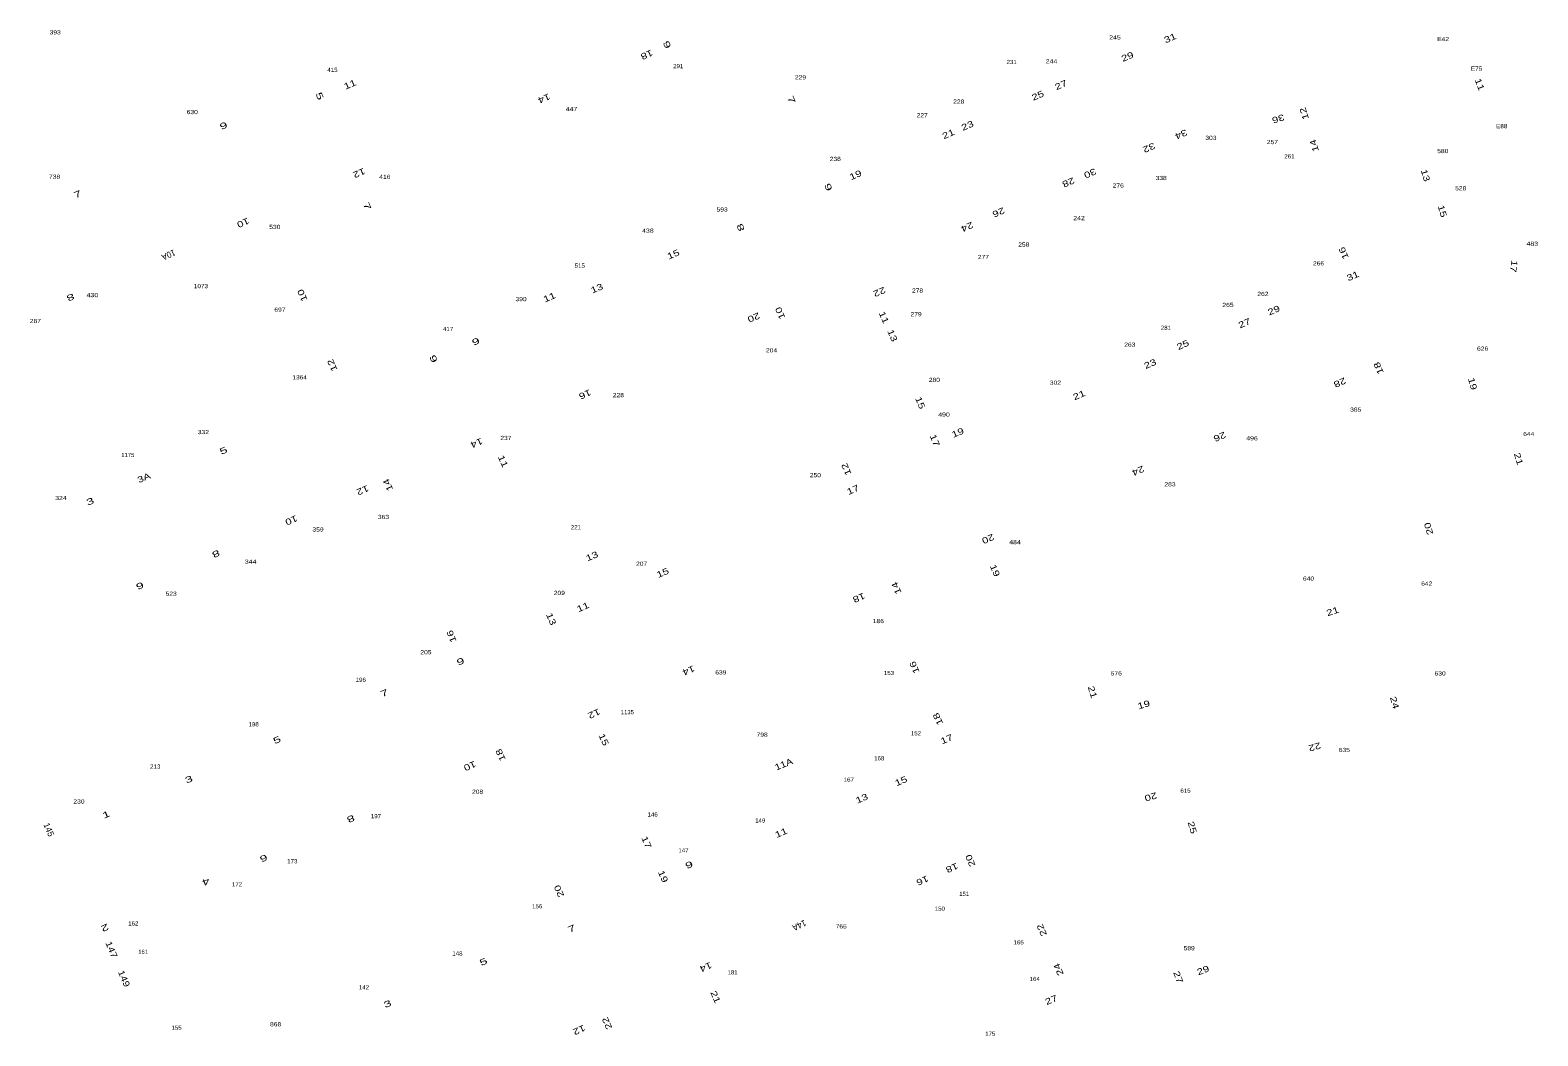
# Model space of a CAD drawing. Extents: x -828673 to -815583, y -1077737 to -1063807.
# Drawn here: x -820515.3 to -820153.1, y -1074088.1 to -1073846.6 of the extents above; entities that cross this region are included whole.
import ezdxf
from ezdxf.enums import TextEntityAlignment as Align

# ---------------------------------------------------------------- set-up
doc = ezdxf.new("R2010")
doc.units = 0
doc.header["$LTSCALE"] = 0.4
doc.layers.add('1', color=7, linetype='Continuous')
doc.layers.add('2', color=7, linetype='Continuous')

msp = doc.modelspace()

# ---------------------------------------------------------------- texts
at = {"layer": '1'}
for s, width, p in [('393', 1.2, (-820509.255, -1073847.574)), ('245', 1.25, (-820254.673, -1073848.798)), ('E42', 1.2, (-820175.857, -1073849.194)), ('291', 1.1, (-820359.582, -1073855.691)), ('231', 1.1, (-820279.5, -1073854.701)), ('244', 1.25, (-820269.913, -1073854.537)), ('415', 1.1, (-820442.65, -1073856.599)), ('229', 1.2, (-820330.22, -1073858.39)), ('E75', 1.15, (-820167.809, -1073856.29)), ('630', 1.2, (-820476.328, -1073866.738)), ('447', 1.25, (-820385.218, -1073866.008)), ('228', 1.2, (-820292.2, -1073864.211)), ('227', 1.2, (-820300.968, -1073867.491)), ('E88', 1.15, (-820161.776, -1073870.112)), ('303', 1.2, (-820231.631, -1073872.926)), ('257', 1.2, (-820216.866, -1073873.941)), ('261', 1.1, (-820212.763, -1073877.37)), ('580', 1.2, (-820175.925, -1073876.105)), ('238', 1.2, (-820321.862, -1073877.985)), ('738', 1.2, (-820509.395, -1073882.263)), ('416', 1.2, (-820430.06, -1073882.293)), ('276', 1.2, (-820253.892, -1073884.373)), ('338', 1.2, (-820243.579, -1073882.568)), ('528', 1.2, (-820171.623, -1073885.038)), ('593', 1.2, (-820349.043, -1073890.125)), ('242', 1.25, (-820263.303, -1073892.21)), ('530', 1.2, (-820456.491, -1073894.32)), ('438', 1.25, (-820366.879, -1073895.215)), ('258', 1.2, (-820276.577, -1073898.554)), ('483', 1.25, (-820154.416, -1073898.357)), ('277', 1.2, (-820286.27, -1073901.543)), ('266', 1.2, (-820205.775, -1073903.082)), ('515', 1.1, (-820383.236, -1073903.609)), ('1073', 1.15, (-820474.234, -1073908.541)), ('278', 1.2, (-820302.105, -1073909.606)), ('430', 1.25, (-820500.328, -1073910.704)), ('390', 1.2, (-820397.343, -1073911.675)), ('265', 1.2, (-820227.528, -1073913.062)), ('262', 1.2, (-820219.131, -1073910.412)), ('287', 1.2, (-820514.008, -1073916.925)), ('697', 1.2, (-820455.26, -1073914.205)), ('279', 1.2, (-820302.444, -1073915.301)), ('417', 1.1, (-820414.871, -1073918.85)), ('281', 1.1, (-820242.435, -1073918.547)), ('204', 1.2, (-820337.172, -1073923.969)), ('263', 1.2, (-820251.113, -1073922.607)), ('626', 1.2, (-820166.357, -1073923.554)), ('1364', 1.15, (-820450.524, -1073930.455)), ('280', 1.2, (-820298.057, -1073931.065)), ('302', 1.2, (-820268.978, -1073931.742)), ('228', 1.2, (-820373.969, -1073934.735)), ('385', 1.2, (-820196.847, -1073938.212)), ('490', 1.25, (-820295.747, -1073939.411)), ('332', 1.2, (-820473.655, -1073943.602)), ('237', 1.2, (-820400.984, -1073945.016)), ('496', 1.25, (-820221.764, -1073945.11)), ('644', 1.2, (-820155.28, -1073944.07)), ('1175', 1.05, (-820491.797, -1073949.114)), ('250', 1.2, (-820326.644, -1073953.956)), ('283', 1.2, (-820241.462, -1073956.146)), ('324', 1.25, (-820507.87, -1073959.44)), ('363', 1.2, (-820430.397, -1073963.989)), ('359', 1.2, (-820446.116, -1073967.004)), ('221', 1.1, (-820384.155, -1073966.463)), ('484', 1.25, (-820278.69, -1073970.041)), ('344', 1.25, (-820462.307, -1073974.749)), ('207', 1.2, (-820368.388, -1073975.237)), ('640', 1.2, (-820208.17, -1073978.8)), ('523', 1.2, (-820481.393, -1073982.436)), ('209', 1.2, (-820388.141, -1073982.238)), ('642', 1.2, (-820179.785, -1073980.004)), ('186', 1.2, (-820311.514, -1073989.009)), ('205', 1.2, (-820420.189, -1073996.494)), ('196', 1.1, (-820435.848, -1074003.115)), ('639', 1.2, (-820349.36, -1074001.335)), ('153', 1.1, (-820308.955, -1074001.487)), ('576', 1.2, (-820254.363, -1074001.574)), ('630', 1.2, (-820176.567, -1074001.584)), ('1135', 1.05, (-820371.813, -1074010.89)), ('198', 1.1, (-820461.584, -1074013.784)), ('798', 1.2, (-820339.426, -1074016.296)), ('152', 1.1, (-820302.466, -1074015.967)), ('168', 1.1, (-820311.307, -1074021.964)), ('635', 1.2, (-820199.575, -1074019.969)), ('213', 1.1, (-820485.221, -1074023.953)), ('167', 1.1, (-820318.62, -1074027.117)), ('615', 1.1, (-820237.734, -1074029.754)), ('230', 1.2, (-820503.539, -1074032.349)), ('208', 1.2, (-820407.787, -1074030.002)), ('197', 1.1, (-820432.198, -1074035.876)), ('146', 1.1, (-820365.743, -1074035.465)), ('149', 1.1, (-820339.89, -1074036.907)), ('147', 1.1, (-820358.327, -1074044.07)), ('173', 1.1, (-820452.283, -1074046.697)), ('172', 1.1, (-820465.57, -1074052.262)), ('156', 1.1, (-820393.47, -1074057.518)), ('150', 1.1, (-820296.749, -1074058.095)), ('162', 1.1, (-820490.496, -1074061.641)), ('765', 1.2, (-820320.439, -1074062.348)), ('148', 1.1, (-820412.628, -1074068.855)), ('165', 1.1, (-820277.81, -1074066.185)), ('589', 1.2, (-820236.847, -1074067.588)), ('164', 1.1, (-820273.958, -1074074.983)), ('142', 1.1, (-820435.082, -1074076.996)), ('155', 1.1, (-820480.093, -1074086.684)), ('868', 1.2, (-820456.3, -1074085.859)), ('175', 1.1, (-820284.635, -1074088.132))]:
    msp.add_text(s, height=1, dxfattribs=dict(at, width=width)).set_placement(p, align=Align.CENTER)
for s, p in [('151', (-820290.899, -1074054.532)), ('161', (-820488.127, -1074068.442)), ('181', (-820346.51, -1074073.377))]:
    msp.add_text(s, height=1, dxfattribs=at).set_placement(p, align=Align.CENTER)
at = {"layer": '2'}
for s, rotation, width, p in [('31', 23.672, 1.35, (-820241.1286, -1073849.1457)), ('18', 203.808, 1.35, (-820367.4337, -1073851.783)), ('6', 113.725, 1.65, (-820361.5915, -1073849.7448)), ('29', 23.714, 1.35, (-820251.3806, -1073853.6025)), ('11', 23.177, 1.35, (-820438.1472, -1073860.292)), ('27', 23.323, 1.35, (-820267.3569, -1073860.4091)), ('11', 291.334, 1.35, (-820167.7648, -1073859.8682)), ('5', 293.526, 1.65, (-820446.3897, -1073862.6861)), ('14', 203.023, 1.35, (-820392.0867, -1073862.2794)), ('25', 23.315, 1.35, (-820272.9288, -1073862.9503)), ('7', 293.311, 1.65, (-820333.073, -1073863.5582)), ('12', 107.321, 1.35, (-820208.5136, -1073866.3878)), ('9', 23.836, 1.65, (-820468.5176, -1073870.2059)), ('23', 23.477, 1.35, (-820289.8098, -1073870.1645)), ('36', 197.479, 1.35, (-820215.6862, -1073867.1526)), ('21', 23.465, 1.35, (-820294.4101, -1073872.1955)), ('34', 203.765, 1.35, (-820239.0708, -1073870.9077)), ('14', 107.113, 1.35, (-820206.1002, -1073874.1017)), ('32', 203.242, 1.35, (-820246.7925, -1073874.1188)), ('12', 203.199, 1.35, (-820436.5171, -1073880.1997)), ('19', 23.597, 1.35, (-820316.6977, -1073882.0324)), ('30', 203.723, 1.35, (-820260.9373, -1073880.2688)), ('13', 287.262, 1.35, (-820180.8, -1073881.6454)), ('9', 292.958, 1.65, (-820324.2268, -1073884.5465)), ('28', 203.658, 1.35, (-820266.156, -1073882.4572)), ('7', 23.409, 1.65, (-820503.593, -1073886.6564)), ('7', 293.098, 1.65, (-820434.9986, -1073889.1308)), ('26', 203.519, 1.35, (-820282.9242, -1073889.6467)), ('15', 287.066, 1.35, (-820176.7439, -1073890.2549)), ('10', 203.639, 1.35, (-820464.3943, -1073892.1518)), ('8', 114.624, 1.65, (-820343.9166, -1073893.6385)), ('24', 203.554, 1.35, (-820290.4773, -1073893.1438)), ('10A', 203.779, 0.95, (-820482.3066, -1073899.8763)), ('15', 23.082, 1.35, (-820360.478, -1073901.1002)), ('16', 112.923, 1.35, (-820199.0518, -1073899.8236)), ('17', 262.282, 1.3, (-820159.599, -1073903.1718)), ('31', 23.599, 1.35, (-820197.2567, -1073906.2964)), ('10', 113.749, 1.35, (-820449.2066, -1073909.9776)), ('13', 22.625, 1.35, (-820378.849, -1073909.2636)), ('22', 203.168, 1.35, (-820311.5524, -1073908.76)), ('8', 203.587, 1.65, (-820505.8704, -1073910.0541)), ('11', 23.619, 1.35, (-820390.2415, -1073911.4047)), ('29', 23.57, 1.35, (-820216.2204, -1073914.5271)), ('20', 202.463, 1.35, (-820341.7229, -1073914.9036)), ('10', 112.96, 1.35, (-820334.4119, -1073914.2556)), ('11', 293.409, 1.35, (-820310.8641, -1073915.86)), ('27', 23.518, 1.35, (-820223.2658, -1073917.6293)), ('13', 293.432, 1.35, (-820308.8233, -1073920.1943)), ('9', 23.76, 1.65, (-820407.9242, -1073922.028)), ('25', 24.131, 1.35, (-820238.0591, -1073922.829)), ('12', 113.714, 1.35, (-820442.0195, -1073926.7606)), ('9', 293.694, 1.65, (-820419.0601, -1073925.7961)), ('23', 23.425, 1.35, (-820245.9492, -1073927.3997)), ('18', 113.377, 1.35, (-820190.6582, -1073927.4696)), ('28', 203.676, 1.35, (-820200.9493, -1073930.5414)), ('19', 286.414, 1.35, (-820169.4815, -1073931.7041)), ('16', 204.082, 1.35, (-820382.276, -1073933.3737)), ('21', 22.996, 1.35, (-820263.0155, -1073934.9145)), ('15', 292.684, 1.35, (-820302.1322, -1073936.3543)), ('14', 203.593, 1.35, (-820408.2993, -1073945.0535)), ('17', 292.446, 1.35, (-820298.641, -1073945.3766)), ('19', 22.769, 1.35, (-820292.1508, -1073943.9388)), ('26', 203.199, 1.35, (-820229.8071, -1073943.5477)), ('5', 23.264, 1.65, (-820468.5267, -1073948.2449)), ('11', 293.813, 1.35, (-820402.3489, -1073950.4147)), ('21', 286.904, 1.35, (-820158.43, -1073949.7639)), ('12', 112.941, 1.35, (-820318.5262, -1073951.7638)), ('24', 203.557, 1.35, (-820249.4063, -1073951.7278)), ('3A', 23.009, 1.3, (-820487.6532, -1073954.7664)), ('12', 203.338, 1.35, (-820435.6779, -1073956.3972)), ('14', 113.699, 1.35, (-820428.6272, -1073955.5224)), ('17', 23.744, 1.35, (-820317.3165, -1073957.6485)), ('3', 23.408, 1.65, (-820500.565, -1073960.4534)), ('10', 203.548, 1.35, (-820452.8139, -1073963.6134)), ('20', 106.907, 1.35, (-820178.62, -1073966.0951)), ('20', 203.162, 1.35, (-820285.4515, -1073968.0829)), ('8', 204.035, 1.65, (-820470.9335, -1073971.6823)), ('13', 22.834, 1.35, (-820380.0265, -1073973.6103)), ('15', 23.415, 1.35, (-820363.023, -1073977.5929)), ('19', 292.71, 1.35, (-820284.1944, -1073976.6455)), ('6', 202.827, 1.65, (-820489.1945, -1073979.3583)), ('18', 203.249, 1.35, (-820316.4539, -1073982.2212)), ('14', 112.73, 1.35, (-820306.4891, -1073980.3218)), ('11', 23.494, 1.35, (-820382.1885, -1073985.8219)), ('21', 18.054, 1.35, (-820202.1609, -1073986.8849)), ('13', 293.106, 1.35, (-820390.7876, -1073988.2977)), ('16', 111.697, 1.35, (-820413.3551, -1073991.9163)), ('9', 23.31, 1.65, (-820411.6048, -1073998.8851)), ('14', 203.244, 1.35, (-820357.3735, -1073999.6918)), ('16', 113.199, 1.35, (-820302.1637, -1073999.3429)), ('7', 23.581, 1.65, (-820429.8805, -1074006.483)), ('21', 286.812, 1.35, (-820260.7883, -1074005.7736)), ('24', 286.52, 1.35, (-820188.2168, -1074008.3172)), ('12', 204.482, 1.35, (-820380.0882, -1074010.0766)), ('18', 114.591, 1.35, (-820296.5314, -1074011.7346)), ('19', 16.676, 1.35, (-820247.5537, -1074009.3059)), ('5', 23.55, 1.65, (-820455.6762, -1074017.7434)), ('15', 294.748, 1.35, (-820378.1599, -1074017.2945)), ('17', 23.199, 1.35, (-820294.8129, -1074017.5583)), ('22', 196.738, 1.35, (-820206.9065, -1074018.0246)), ('18', 114.028, 1.35, (-820401.5834, -1074020.3954)), ('10', 203.341, 1.35, (-820409.9218, -1074022.6243)), ('11A', 22.348, 1.25, (-820333.9532, -1074023.5893)), ('3', 21.098, 1.65, (-820476.8865, -1074027.223)), ('15', 23.684, 1.35, (-820305.7663, -1074027.6212)), ('13', 23.614, 1.35, (-820315.1919, -1074031.796)), ('20', 196.037, 1.35, (-820246.2788, -1074030.0247)), ('1', 23.508, 1.65, (-820496.7147, -1074035.6649)), ('8', 203.985, 1.65, (-820438.5486, -1074035.3325)), ('11', 23.626, 1.35, (-820334.5786, -1074040.0415)), ('25', 286.548, 1.35, (-820236.8142, -1074038.3029)), ('17', 293.686, 1.35, (-820367.8961, -1074041.9357)), ('6', 203.235, 1.65, (-820459.4726, -1074044.7888)), ('9', 24.541, 1.65, (-820356.6795, -1074047.7469)), ('18', 203.747, 1.35, (-820294.1215, -1074047.1165)), ('20', 113.15, 1.35, (-820288.7276, -1074045.7654)), ('4', 201.952, 1.65, (-820473.3216, -1074050.4635)), ('19', 294.152, 1.35, (-820363.9017, -1074050.1521)), ('16', 203.728, 1.35, (-820301.2062, -1074050.1699)), ('20', 113.775, 1.35, (-820387.54, -1074053.0884)), ('2', 204.113, 1.65, (-820497.6201, -1074061.5095)), ('7', 24.036, 1.65, (-820384.8825, -1074063.0617)), ('14A', 205.032, 0.95, (-820330.8312, -1074060.9294)), ('22', 113.392, 1.35, (-820271.5695, -1074062.4408)), ('147', 293.219, 1.25, (-820496.4001, -1074067.7298)), ('5', 23.645, 1.65, (-820406.0838, -1074071.0319)), ('14', 203.644, 1.35, (-820353.2542, -1074070.9399)), ('24', 113.307, 1.35, (-820267.5575, -1074071.9077)), ('29', 21.561, 1.35, (-820233.2431, -1074073.0833)), ('149', 293.218, 1.25, (-820493.3921, -1074074.6858)), ('27', 291.736, 1.35, (-820240.1588, -1074074.3218)), ('21', 293.719, 1.35, (-820351.3063, -1074079.1043)), ('27', 22.786, 1.35, (-820269.6945, -1074080.1886)), ('3', 22.627, 1.65, (-820429.1345, -1074081.1589)), ('12', 204.657, 1.35, (-820383.6896, -1074086.0449)), ('22', 113.656, 1.35, (-820376.0072, -1074084.8389))]:
    msp.add_text(s, height=1.5, rotation=rotation, dxfattribs=dict(at, width=width)).set_placement(p, align=Align.CENTER)
msp.add_text('145', height=1.5, rotation=293.179, dxfattribs=at).set_placement((-820511.4582, -1074038.9118), align=Align.CENTER)

doc.saveas('drawing.dxf')
